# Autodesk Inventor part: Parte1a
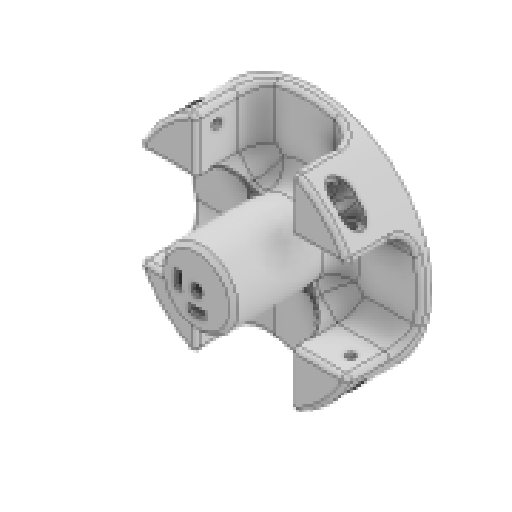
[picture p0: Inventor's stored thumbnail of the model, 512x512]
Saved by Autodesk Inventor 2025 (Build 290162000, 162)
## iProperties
Created: 2025-05
Part Number: Parte1a
Material: Generico
Document SubType Name: Modeling
Designer: R5800u
Density: 1 g/cm^3
Appearance: Default
Author: R5800u
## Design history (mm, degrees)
sketch "Schizzo1" dims "d0" = 100
  geometry: L1 (0, 0)-(35.355, 35.355); L2 (0, 0)-(50, 0); L3 (20.572, 20.572)-(20.572, 45.572); L4 (20.572, 20.572)-(45.572, 20.572); L5 (0, 0)-(0, 44.829) reference; L6 (-20.572, 20.572)-(-20.572, 45.572); L7 (0, 0)-(-35.355, 35.355); L8 (-20.572, 20.572)-(-45.572, 20.572); L9 (0, 0)-(56.569, 0); L10 (26.572, 42.355)-(26.572, 26.572); L11 (26.572, 26.572)-(42.355, 26.572); L12 (-26.572, 42.355)-(-26.572, 26.572); L13 (-26.572, 26.572)-(-42.355, 26.572); L14 (-20.572, 24.815)-(0, 4.243); L15 (0, 4.243)-(20.572, 24.815); L16 (24.815, 20.572)-(0, -4.243); L17 (0, -4.243)-(-24.815, 20.572); L18 (20.572, -20.572)-(20.572, -45.572); L19 (0, -4.243)-(20.572, -24.815); L20 (26.572, -42.355)-(26.572, -26.572); L21 (24.815, -20.572)-(0, 4.243); L22 (0, 0)-(35.355, -35.355); L23 (26.572, -26.572)-(42.355, -26.572); L24 (20.572, -20.572)-(45.572, -20.572); L25 (0, 0)-(0, -44.829); L26 (-20.572, -24.815)-(0, -4.243); L27 (0, 4.243)-(-24.815, -20.572); L28 (0, 0)-(-35.355, -35.355); L29 (-20.572, -20.572)-(-20.572, -45.572); L30 (-26.572, -42.355)-(-26.572, -26.572); L31 (-26.572, -26.572)-(-42.355, -26.572); L32 (-20.572, -20.572)-(-45.572, -20.572); 3 further points
  constraints: 64 end point, 25 symmetric about line, 13 point on line, 3 vertical, 2 coincident, 2 horizontal, 1 equal length, 9 other
  dimensions: "d1" = 45 deg angle of L2 L1; "d3" = 25 distance of L3.start L4.end; "d8" = 6 distance between parallel lines of L3 L10; "d9" = 6 distance between parallel lines of L6 L12; "d10" = 3 distance between parallel lines of L7 L14; "d11" = 3 distance between parallel lines of L1 L16; "d22" = 6 distance between parallel lines of L4 L11; "d23" = 6 distance between parallel lines of L8 L13
extrude "Estrusione1" new body sketch "Schizzo1" stored distance "d4" = 75; taper "d5" = 0 deg
node "Piano di lavoro1"
sketch "Schizzo3" dims "d24" = 100
  geometry: L1 (0, 0)-(35.355, 35.355); L2 (0, 0)-(50, 0); L3 (20.572, 20.572)-(20.572, 45.572); L4 (20.572, 20.572)-(45.572, 20.572); L5 (0, 0)-(0, 44.829); L6 (-20.572, 20.572)-(-20.572, 45.572); L7 (0, 0)-(-35.355, 35.355); L8 (-20.572, 20.572)-(-45.572, 20.572); L9 (0, 0)-(56.569, 0); L10 (26.572, 42.355)-(26.572, 26.572); L11 (26.572, 26.572)-(42.355, 26.572); L12 (-26.572, 42.355)-(-26.572, 26.572); L13 (-26.572, 26.572)-(-42.355, 26.572); L14 (-20.572, 24.815)-(0, 4.243); L15 (0, 4.243)-(20.572, 24.815); L16 (24.815, 20.572)-(0, -4.243); L17 (0, -4.243)-(-24.815, 20.572); L18 (20.572, -20.572)-(20.572, -45.572); L19 (0, -4.243)-(20.572, -24.815); L20 (26.572, -42.355)-(26.572, -26.572); L21 (24.815, -20.572)-(0, 4.243); L22 (0, 0)-(35.355, -35.355); L23 (26.572, -26.572)-(42.355, -26.572); L24 (20.572, -20.572)-(45.572, -20.572); L25 (0, 0)-(0, -44.829); L26 (-20.572, -24.815)-(0, -4.243); L27 (0, 4.243)-(-24.815, -20.572); L28 (0, 0)-(-35.355, -35.355); L29 (-20.572, -20.572)-(-20.572, -45.572); L30 (-26.572, -42.355)-(-26.572, -26.572); L31 (-26.572, -26.572)-(-42.355, -26.572); L32 (-20.572, -20.572)-(-45.572, -20.572); 16 further points
  constraints: 64 end point, 25 symmetric about line, 13 point on line, 2 coincident, 2 horizontal, 2 parallel, 2 vertical, 1 equal length, 9 other
  dimensions: "d25" = 45 deg angle of L2 L1; "d26" = 25 distance of L3.start L4.end; "d27" = 6 distance between parallel lines of L3 L10; "d28" = 6 distance between parallel lines of L6 L12; "d29" = 3 distance between parallel lines of L7 L14; "d30" = 3 distance between parallel lines of L1 L16; "d31" = 6 distance between parallel lines of L4 L11; "d32" = 6 distance between parallel lines of L8 L13; "d41" = 3 distance between parallel lines of L1 L15; "d42" = 3 distance between parallel lines of L7 L17; "d63" = 25 distance of L18.start L24.end (derived); "d64" = 25 distance of L18.start L18.end (derived); "d65" = 41.14378 distance between parallel lines of L32 L8 (derived); "d66" = 41.14378 distance between parallel lines of L24 L4 (derived); "d67" = 41.14378 distance between parallel lines of L3 L6 (derived); "d68" = 41.14378 distance between parallel lines of L18 L29 (derived)
extrude "Estrusione4" cut sketch "Schizzo3" extent not by distance; stored distance "d33" = 30; taper "d34" = 0 deg
sketch "Schizzo4"
  geometry: L1 (45.572, 37.5)-(45.572, 3) reference; L2 (45.572, 20.25)-(0, 20.25); L3 (0, 3)-(0, 37.5) reference; C1 r 2 at (37, 20.25); 2 further points
  constraints: 2 end point, 2 midpoint, 1 centre point, 1 coincident, 1 point on line
  dimensions: "d36" = 37 horizontal distance of point (0, 0) point (37, 20.25); "d37" = 4 diameter of C1
extrude "Estrusione5" cut sketch "Schizzo4" extent not by distance; stored distance "d38" = 0; taper "d39" = 0 deg
pattern_circular "Serie circolare1" dims angle "d47" = 360 deg
sketch "Schizzo5"
  geometry: C1 r 50 at (0, 0) reference; 1 further point
extrude "Estrusione6" cut sketch "Schizzo5" distance "d53" = 36; taper "d54" = 0 deg
sketch "Schizzo6"
  geometry: L1 (45.572, -20.572)-(20.572, -20.572) reference; L2 (20.572, 20.572)-(45.572, 20.572) reference; L3 (20.572, 45.572)-(20.572, 20.572) reference; L4 (-20.572, 20.572)-(-20.572, 45.572) reference; L5 (-45.572, 20.572)-(-20.572, 20.572) reference; L6 (-20.572, -20.572)-(-45.572, -20.572) reference; L7 (-20.572, -45.572)-(-20.572, -20.572) reference; L8 (20.572, -20.572)-(20.572, -45.572) reference; L9 (-20.572, 24.815)-(-24.815, 20.572); L10 (-24.815, 20.572)-(-20.572, 24.815); L11 (-24.815, -20.572)-(-20.572, -24.815); L12 (20.572, 24.815)-(24.815, 20.572); L13 (24.815, -20.572)-(20.572, -24.815); C1 r 16 at (0, 0); A1 r 50 centre (0, 0) between (45.572, 20.572) and (20.572, 45.572) reference; A2 r 50 centre (0, 0) between (-20.572, 45.572) and (-45.572, 20.572) reference; A3 r 50 centre (0, 0) between (-45.572, -20.572) and (-20.572, -45.572) reference; A4 r 50 centre (0, 0) between (20.572, -45.572) and (45.572, -20.572) reference; A5 r 35 centre (0, 53.131) between (-20.572, 24.815) and (20.572, 24.815); A6 r 35 centre (-53.131, 0) between (-24.815, -20.572) and (-24.815, 20.572); A7 r 35 centre (0, -53.131) between (20.572, -24.815) and (-20.572, -24.815); A8 r 35 centre (53.131, 0) between (24.815, 20.572) and (24.815, -20.572); 1 further point
  constraints: 10 end point, 8 point on circle, 5 centre point, 1 coincident, 1 parallel, 1 perpendicular, 17 other
  dimensions: "d55" = 32 diameter of C1; "d109" = 35 radius of A5; "d112" = 360 deg dimension on point (0, 0) A5.centre (derived)
extrude "Estrusione7" join sketch "Schizzo6" stored distance "d56" = 36; taper "d57" = 0 deg
sketch "Schizzo7"
  geometry: C1 r 2.5 at (0, 0); 1 further point
  constraints: 1 centre point, 1 coincident
  dimensions: "d69" = 5 diameter of C1
extrude "Estrusione8" cut sketch "Schizzo7" extent not by distance; stored distance "d70" = 10; taper "d71" = 0 deg
sketch "Schizzo8"
  geometry: L1 (20.572, 20.572)-(45.572, 20.572) reference; L2 (20.572, 45.572)-(20.572, 20.572) reference; L3 (-20.572, 20.572)-(-20.572, 45.572) reference; L4 (-45.572, 20.572)-(-20.572, 20.572) reference; L5 (-20.572, -20.572)-(-45.572, -20.572) reference; L6 (-20.572, -45.572)-(-20.572, -20.572) reference; L7 (20.572, -20.572)-(20.572, -45.572) reference; L8 (45.572, -20.572)-(20.572, -20.572) reference; A1 r 50 centre (0, 0) between (45.572, 20.572) and (20.572, 45.572) reference; A2 r 50 centre (0, 0) between (20.572, -45.572) and (45.572, -20.572) reference; A3 r 50 centre (0, 0) between (-45.572, -20.572) and (-20.572, -45.572) reference; A4 r 50 centre (0, 0) between (-20.572, 45.572) and (-45.572, 20.572) reference; A5 r 35 centre (0, 53.131) between (-20.572, 24.815) and (20.572, 24.815); A6 r 35 centre (-53.131, 0) between (-24.815, -20.572) and (-24.815, 20.572); A7 r 35 centre (0, -53.131) between (20.572, -24.815) and (-20.572, -24.815); A8 r 35 centre (53.131, 0) between (24.815, 20.572) and (24.815, -20.572); 9 further points
  constraints: 8 point on circle, 4 centre point, 17 other
  dimensions: "d104" = 35 radius of A5; "d107" = 360 deg dimension on point (0, 0) A5.centre (derived)
extrude "Estrusione9" cut sketch "Schizzo8" distance "d72" = 8; taper "d73" = 0 deg
node "Piano di lavoro3"
sketch "Schizzo10"
  geometry: C1 r 2 at (-17.25, 8.572) reference; C2 r 4.25 at (-17.25, 8.572); 1 further point
  constraints: 1 centre point, 1 coincident
  dimensions: "d86" = 8.5 diameter of C2
extrude "Estrusione11" cut sketch "Schizzo10" distance "d87" = 13; taper "d88" = 0 deg
node "Piano di lavoro4"
sketch "Schizzo11"
  geometry: C1 r 2 at (8.572, -17.25) reference; C2 r 4.25 at (8.572, -17.25); 1 further point
  constraints: 1 centre point, 1 coincident
  dimensions: "d90" = 8.5 diameter of C2
extrude "Estrusione12" cut sketch "Schizzo11" distance "d91" = 13; taper "d92" = 0 deg
pattern_circular "Serie circolare4" dims "d94" = 360 deg
sketch "Schizzo12"
  geometry: C1 r 2.5 at (0, 0) reference; C2 r 6 at (0, 0); 1 further point
  constraints: 1 centre point, 1 coincident
  dimensions: "d128" = 12 diameter of C2
extrude "Estrusione13" cut sketch "Schizzo12" distance "d129" = 13; taper "d130" = 0 deg
sketch "Schizzo14"
  geometry: C1 r 6 at (0, 0) reference; C2 r 16 at (0, 0) reference; C3 r 2.5 at (0, 0) reference; C4 r 20 at (0, 0); 1 further point
  constraints: 1 centre point, 1 coincident
  dimensions: "d133" = 40 diameter of C4
extrude "Estrusione14" cut sketch "Schizzo14" distance "d131" = 15; taper "d132" = 0 deg
sketch "Schizzo17"
  geometry: L1 (-45.572, -20.572)-(-20.572, -20.572) reference; L2 (-20.572, -20.572)-(-20.572, -45.572) reference; L3 (20.572, -45.572)-(20.572, -20.572) reference; L4 (20.572, -20.572)-(45.572, -20.572) reference; L5 (45.572, 20.572)-(20.572, 20.572) reference; L6 (20.572, 20.572)-(20.572, 45.572) reference; L7 (-20.572, 45.572)-(-20.572, 20.572) reference; L8 (-20.572, 20.572)-(-45.572, 20.572) reference; L9 (20.572, 20.572)-(0, 0); L10 (21.986, 20.572)-(0.707, -0.707); L11 (20.572, 21.986)-(-0.707, 0.707); C1 r 16 at (0, 0) reference; C2 r 2.5 at (0, 0) reference; A1 r 50 centre (0, 0) between (-20.572, -45.572) and (20.572, -45.572) reference; A2 r 50 centre (0, 0) between (45.572, -20.572) and (45.572, 20.572) reference; A3 r 50 centre (0, 0) between (20.572, 45.572) and (-20.572, 45.572) reference; A4 r 50 centre (0, 0) between (-45.572, 20.572) and (-45.572, -20.572) reference; 3 further points
  constraints: 6 end point, 2 parallel, 2 point on line
  dimensions: "d149" = 1 distance between parallel lines of L9 L10; "d150" = 1 distance between parallel lines of L9 L11
extrude "Estrusione16" join sketch "Schizzo17" distance "d151" = 10; taper "d152" = 0 deg
pattern_circular "Serie circolare9" dims angle "d154" = 360 deg
fillet "Raccordo32" dims "d164" = 8
fillet "Raccordo33" dims "d165" = 9.9
fillet "Raccordo34" dims "d166" = 2
fillet "Raccordo35" dims "d167" = 2
fillet "Raccordo36" dims "d168" = 1
fillet "Raccordo38" dims "d170" = 3
sketch "Schizzo18"
  geometry: C1 r 2.5 at (0, 0) reference; C2 r 16 at (0, 0); C3 r 2.5 at (0, 0); 1 further point
  constraints: 2 centre point, 2 coincident
  dimensions: "d171" = 5 diameter of C3
extrude "Estrusione17" join sketch "Schizzo18" distance "d172" = 35; taper "d173" = 0 deg
chamfer "Smusso1" distance "d174" = 2; stored, may be unused: second distance "d175" = 2, angle "d176" = 45 deg
fillet "Raccordo39" dims "d177" = 5
sketch "Schizzo19"
  geometry: L1 (-9.7, -3.6)-(-6.3, -3.6); L2 (-6.3, -3.6)-(-6.3, 3.6); L3 (-6.3, 3.6)-(-9.7, 3.6); L4 (-9.7, 3.6)-(-9.7, -3.6); L5 (-9.7, -3.6)-(-6.3, 3.6); L6 (-6.3, -3.6)-(-9.7, 3.6); 2 further points
  constraints: 12 end point, 2 midpoint, 2 parallel, 1 horizontal, 1 perpendicular
  dimensions: "d178" = 3.4 distance of L3.end L2.end; "d179" = 7.2 distance of L2.end L1.end; "d180" = 8 distance of point (0, 0) point (-8, 0)
extrude "Estrusione18" cut sketch "Schizzo19" distance "d181" = 18; taper "d182" = 0 deg
sketch "Schizzo20"
  geometry: L1 (-15.5, -3.969)-(-15.5, 3.969); A1 r 16 centre (0, 0) between (-15.5, -3.969) and (-15.5, 3.969) reference; 1 further point
  constraints: 2 end point, 2 point on circle, 1 vertical
  dimensions: "d183" = 15.5 distance from line of point (0, 0) L1
extrude "Estrusione19" cut sketch "Schizzo20" distance "d184" = 18; taper "d185" = 0 deg
sketch "Schizzo22"
  geometry: L1 (-2.1, -1.356)-(-2.1, 1.356); A1 r 2.5 centre (0, 0) between (-2.1, -1.356) and (-2.1, 1.356) reference; 1 further point
  constraints: 2 end point, 2 point on circle, 1 vertical
  dimensions: "d194" = 2.1 distance from line of point (0, 0) L1
node "Piano di lavoro5"
extrude "Estrusione20" join sketch "Schizzo22" stored distance "d195" = 0; taper "d196" = 0 deg
sketch "Schizzo21"
  geometry: L1 (-20.5, 11.578)-(-20.5, -3.641) reference; L2 (-20.5, 3.969)-(16, 3.969); L3 (16, -12.031)-(16, 19.969) reference; 4 further points
  constraints: 2 end point, 2 midpoint, 1 point on line
  dimensions: "d186" = 8 distance from line of L3 point (8, 3.969)
hole "Foro3" sketch "Schizzo21" at (8, 3.969) diameter "d197" = 4.3; stored, may be unused: countersink angle "d201" = 90 deg, drill point angle "d203" = 118 deg; dims "d198" = 6, "d199" = 4, "d200" = 2, "d202" = 8
fillet "Raccordo40" dims "d204" = 1.2
pattern_circular "Serie circolare11" dims "d206" = 90 deg
fillet "Raccordo41" dims "d208" = 0.2
feature "ۇ耀ۉ耀ۋ耀ۍ耀ۏ耀ۑ耀ۓ耀ە耀" dims "d0" = 100, "d1" = 45 deg, "d3" = 25, "d4" = 75, "d5" = 0, "d8" = 6, "d9" = 6, "d10" = 3, "d11" = 3, "d12" = 3, "d18" = 2, "d19" = 2, "d22" = 6, "d23" = 6, "d24" = 100, "d25" = 45 deg, "d26" = 25, "d27" = 6, "d28" = 6, "d29" = 3, "d30" = 3, "d31" = 6, "d32" = 6, "d33" = 30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
node "Solido1"
node "Linea chiusa proiettata1"
node "Schizzo - Serie circolare1" dims "d107" = 360 deg (derived)
node "Linea chiusa proiettata2"
node "Schizzo - Serie circolare2" dims "d112" = 360 deg (derived)
node "Linea chiusa proiettata3"
node "Linea chiusa proiettata4"
